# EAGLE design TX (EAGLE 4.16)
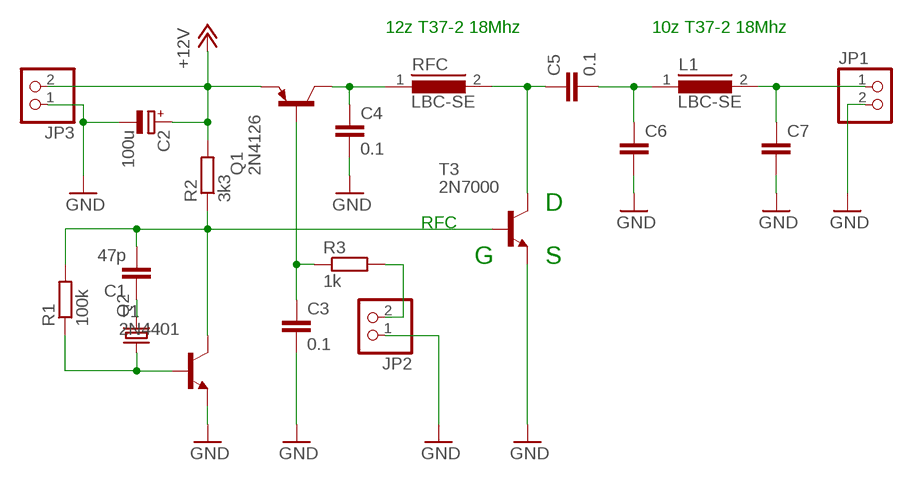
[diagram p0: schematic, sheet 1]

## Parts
C1  47p  C-EU050-025X075  [C050-025X075]
C2  100u  CPOL-EUE3.5-8  [E3,5-8]
C3  0.1  C-EUC1206  [C1206]
C4  0.1  C-EUC1206  [C1206]
C5  0.1  C-EUC1206  [C1206]
C6  C-EU050-025X075  [C050-025X075]
C7  C-EU050-025X075  [C050-025X075]
JP1  PINHD-1X2  [1X02]
JP2  PINHD-1X2  [1X02]
JP3  PINHD-1X2  [1X02]
L1  LBC-SE  [LBC-SE]
Q1  2N4126  [TO92-CBE]
Q2  CRYSTALHC49S  [HC49/S]
R1  100k  R-EU_M1206  [M1206]
R2  3k3  R-EU_M1206  [M1206]
R3  1k  R-EU_0207/7  [0207/7]
RFC  LBC-SE  [LBC-SE]
T1  2N4401  2N4124-NPN-TO92-CBE  [TO92-CBE]
T3  2N7000  2N4124-NPN-TO92-CBE  [TO92-CBE]

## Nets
+12V: C2.+ JP3.2 Q1.E R2.2
GND: C2.- C3.2 C4.2 C6.2 C7.2 JP1.2 JP2.1 JP3.1 T1.E T3.E
N$1: C1.2 R1.2 R2.1 T1.C T3.B
N$2: C3.1 Q1.B R3.1
N$3: JP2.2 R3.2
N$4: C4.1 Q1.C RFC.1
N$5: C1.1 Q2.2
N$6: Q2.1 R1.1 T1.B
N$7: C5.1 RFC.2 T3.C
N$8: C5.2 C6.1 L1.1
N$9: C7.1 JP1.1 L1.2

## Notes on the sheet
- 12z T37-2 18Mhz | 10z T37-2 18Mhz
- D
- RFC
- G | S

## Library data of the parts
C1 C3-C7 = rcl:C-EU: CAPACITOR, European symbol
C2 = rcl:CPOL-EU: POLARIZED CAPACITOR, European symbol
JP1-JP3 = pinhead1:PINHD-1X2: PIN HEADER
L1 RFC = inductors:LBC-SE: INDUCTOR
Q1 = transistor-pnp:2N4126*: PNP Transistror
Q2 = crystal:CRYSTAL: CRYSTAL
R1-R3 = rcl:R-EU_: RESISTOR, European symbol
T1 T3 = transistor:*-NPN-: NPN Transistror

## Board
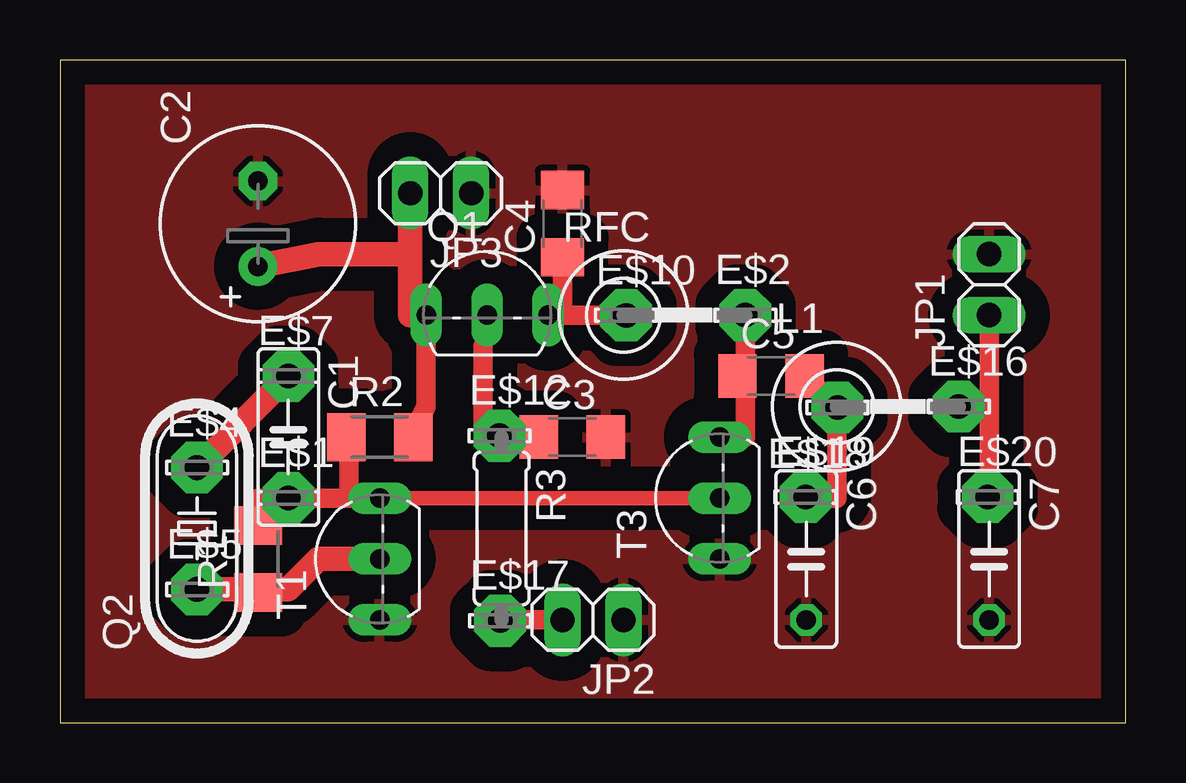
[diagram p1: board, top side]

Size 44.43 x 27.61 mm. Coordinates in mm from the lower left corner, seen from the top.
Outline: 0,0 44.43,0 44.43,27.61 0,27.61 0,0
Copper layers (1*16): Top 0.035mm / dielectric 1.5mm / Bottom 0.035mm
Design rules "default": minimum track width 10mil, minimum drill 24mil, track to track 8mil, track to pad 8mil, pad to pad 8mil, via to via 8mil, smd to smd 8mil, copper to edge 40mil, drill to drill 8mil, minimum pad ring 10mil, minimum via ring 8mil, stop-mask expansion 4mil, vias tented up to drill 0mil, thermal gap 10mil

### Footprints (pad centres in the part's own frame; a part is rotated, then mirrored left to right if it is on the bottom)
C050-025X075 = drill 0.813 octagon: 1 -2.54,0; 2 2.54,0
E3,5-8 = drill 0.813 pad 1.6 round: + -1.778,0 | drill 0.813 pad 1.6 octagon: - 1.778,0
C1206 = smd 1.6 x 1.8: 1 -1.4,0; 2 1.4,0
LSP10 = drill 1.016 pad 2.159 octagon: MP 0,0
1X02 = drill 1.016 long: 1 -1.27,0; 2 1.27,0
LBC-SE = drill 0.914 octagon: 1 -2.54,0; 2 2.54,0
TO92-CBE = drill 0.813 long: B 0,0; C 2.54,0; E -2.54,0
HC49/S = drill 0.813 round: 1 -2.413,0; 2 2.413,0
M1206 = smd 1.6 x 2: 1 -1.4,0; 2 1.4,0
0207/7 = drill 0.813 octagon: 1 -3.81,0; 2 3.81,0

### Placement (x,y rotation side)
C1  9.52,11.9 270 top
C2  8.25,20.79 90 top
C3  21.35,11.9 0 top
C4  20.95,20.79 90 top
C5  29.64,14.44 0 top
C6  31.11,6.82 270 top
C7  38.73,6.82 270 top
E$1  [LSP10]  9.52,9.36 0 top
E$2  [LSP10]  28.57,16.98 0 top
E$4  [LSP10]  5.71,10.63 0 top
E$5  [LSP10]  5.71,5.55 0 top
E$7  [LSP10]  9.52,14.44 0 top
E$10  [LSP10]  23.6,16.97 0 top
E$12  [LSP10]  18.32,11.96 0 top
E$16  [LSP10]  37.46,13.17 0 top
E$17  [LSP10]  18.35,4.25 0 top
E$18  [LSP10]  32.41,13.13 180 top
E$19  [LSP10]  31.08,9.4 0 top
E$20  [LSP10]  38.67,9.4 0 top
JP1  38.73,18.25 90 top
JP2  22.22,4.28 180 top
JP3  15.87,22.06 180 top
L1  34.92,13.17 0 top
Q1  17.81,16.98 0 top
Q2  5.71,8.09 90 top
R1  8.25,6.82 90 top
R2  13.33,11.9 0 top
R3  18.41,8.09 270 top
RFC  26.03,16.98 0 top
T1  13.33,6.82 90 top
T3  27.5,9.36 90 top

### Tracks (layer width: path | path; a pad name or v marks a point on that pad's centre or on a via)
+12V
  Top 0.254: 14.6,11.9 R2.2
  Top 0.813: 14.6,11.9 15.27,13.17 Q1.E
  Top 1.016: 14.6,19.52 14.6,16.98 Q1.E | 14.6,19.52 10.79,19.52 C2.+ | 14.6,19.52 JP3.2
GND
  pour Top (isolate 1.016): 0.63,27.14 43.81,27.14 43.81,0.47 0.63,0.47
N$1
  Top 0.254: R1.2 8.25,8.09 | 12.06,11.9 R2.1
  Top 0.61: 12.06,9.36 T1.C T3.B
  Top 0.813: 12.06,9.36 12.06,11.9 | 12.06,9.36 C1.2 | R1.2 8.25,9.36 12.06,9.36
N$2
  Top 0.254: 17.64,15.71 17.71,16.98 Q1.B
  Top 0.813: 17.64,15.71 17.64,11.9 R3.1 C3.1
N$3
  Top 0.813: R3.2 JP2.2
N$4
  Top 0.254: C4.1 20.95,19.52
  Top 0.813: 20.95,19.52 20.95,16.98 | 20.95,16.98 Q1.C | 20.95,16.98 RFC.1
N$5
  Top 1.016: C1.1 5.71,10.63 Q2.2
N$6
  Top 0.254: Q2.1 5.71,5.55 | 8.25,5.55 R1.1
  Top 1.016: 5.71,5.55 8.25,5.55 9.52,5.55 10.79,6.82 T1.B
N$7
  Top 0.254: 28.57,14.44 C5.1
  Top 0.813: RFC.2 28.57,14.44 28.57,11.9 T3.C
N$8
  Top 0.254: 31.11,14.44 C5.2
  Top 0.813: 31.11,14.44 L1.1 32.38,9.36 C6.1
N$9
  Top 0.813: 38.73,13.17 JP1.1 | C7.1 38.73,13.17 | 38.73,13.17 L1.2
